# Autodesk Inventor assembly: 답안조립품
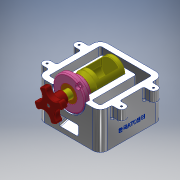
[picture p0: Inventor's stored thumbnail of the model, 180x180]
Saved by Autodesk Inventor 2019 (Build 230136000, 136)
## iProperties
Created: 2022-03
Part Number: 답안조립품
Material: 일반
Document SubType Name: Assembly
Designer: LINE501-1
Author: LINE501-1
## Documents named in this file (8)
- C:\Users\LINE501-1\Desktop\720306V1007\답안조립품.iam
- C:\Users\LINE501-1\Desktop\720306V1007\본체.ipt
- C:\Users\LINE501-1\Desktop\720306V1007\본체커버.ipt
- C:\Users\LINE501-1\Desktop\720306V1007\핸들축.ipt
- C:\Users\LINE501-1\Desktop\720306V1007\베어링 부시.ipt
- C:\Users\LINE501-1\Desktop\720306V1007\앞커버.ipt
- C:\Users\LINE501-1\Desktop\720306V1007\핸들.ipt
- C:\Users\LINE501-1\Desktop\720306V1007\볼트 M3x12.ipt
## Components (2 placed, 2 different names)
1. 핸들축:1 — 각도:1
2. 핸들:1
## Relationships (1: Angle 1)
- 각도:1 [Angle]: 핸들축:1
